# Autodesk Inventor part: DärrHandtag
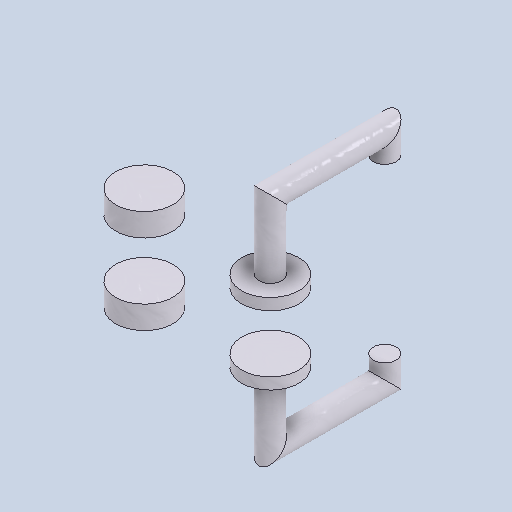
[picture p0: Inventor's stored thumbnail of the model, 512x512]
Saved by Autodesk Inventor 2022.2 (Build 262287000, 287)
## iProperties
Created: 2019-06
Part Number: DärrHandtag
Material: Aluminum 6061, Welded
Document SubType Name: Modeling
Designer: cl
Density: 2.7 g/cm^3
Appearance: Weld - Aluminum
Author: cl
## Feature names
1. Extrusion1
2. Extrusion2
3. Sweep1
4. Mirror1
## Parameters: d7 = 0, d10 = 0, d12 = 0, d18 = 0, d19 = 0, d20 = 25 mm
